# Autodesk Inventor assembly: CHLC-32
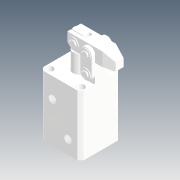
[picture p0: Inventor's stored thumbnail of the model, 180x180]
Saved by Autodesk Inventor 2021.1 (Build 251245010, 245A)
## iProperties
Created: 2019-04
Part Number: CHLC-32
Description: STEP AP214
Document SubType Name: Assembly
Designer: user
Title: CHLC-32.STEP
Revision Number: ÈÎºÎ
Sending System: SolidWorks 2016
Preprocessor: SwSTEP 2.0
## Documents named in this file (8)
- D:\Vault_2016\Projekty\Clamptek\Hydraulic\CHLC\CHLC-32\Inventor\CHLC-32\CHLC-32.iam
- D:\Vault_2016\Projekty\Clamptek\Hydraulic\CHLC\CHLC-32\Inventor\CHLC-32\CHLC-32-05.ipt
- D:\Vault_2016\Projekty\Clamptek\Hydraulic\CHLC\CHLC-32\Inventor\CHLC-32\CHLC-32-08.ipt
- D:\Vault_2016\Projekty\Clamptek\Hydraulic\CHLC\CHLC-32\Inventor\CHLC-32\CHLC-32-03.ipt
- D:\Vault_2016\Projekty\Clamptek\Hydraulic\CHLC\CHLC-32\Inventor\CHLC-32\CHLC-32-02.ipt
- D:\Vault_2016\Projekty\Clamptek\Hydraulic\CHLC\CHLC-32\Inventor\CHLC-32\CHLC-32-04.ipt
- D:\Vault_2016\Projekty\Clamptek\Hydraulic\CHLC\CHLC-32\Inventor\CHLC-32\LHC01D-40-08.ipt
- D:\Vault_2016\Projekty\Clamptek\Hydraulic\CHLC\CHLC-32\Inventor\CHLC-32\Ñ¹±Û_1.ipt
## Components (14 placed, 14 different names)
1. CHLC-32-05_1
2. CHLC-32-08_2
3. CHLC-32-03_3
4. CHLC-32-03_4
5. CHLC-32-02_5
6. CHLC-32-04_6
7. CHLC-32-04_7
8. LHC01D-40-08_8
9. LHC01D-40-08_9
10. LHC01D-40-08_10
11. LHC01D-40-08_11
12. LHC01D-40-08_12
13. LHC01D-40-08_13
14. Ñ¹±Û_1_14
